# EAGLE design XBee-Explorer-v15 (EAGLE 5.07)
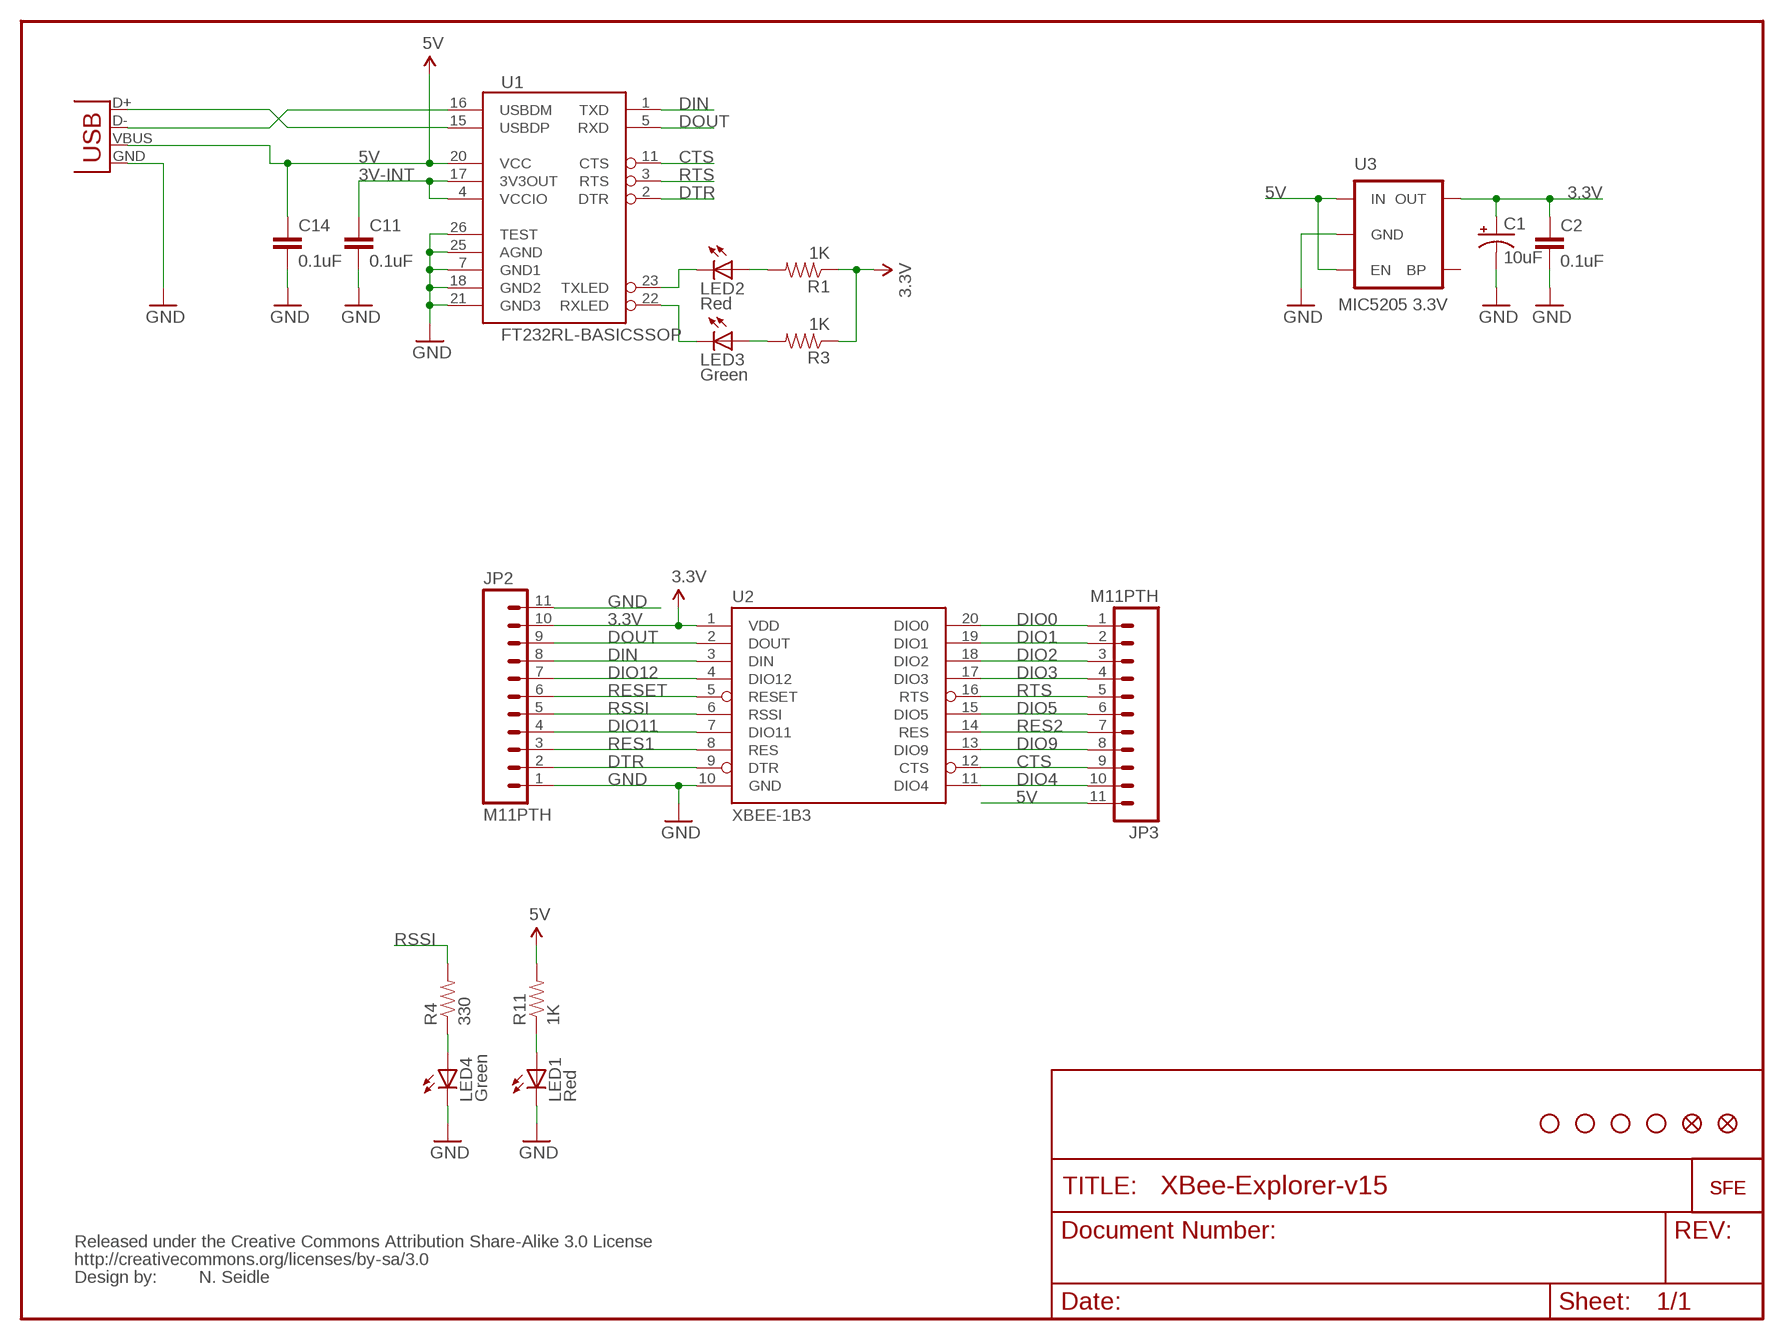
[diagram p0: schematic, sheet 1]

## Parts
C1  10uF  CAP_POL1206  [EIA3216]
C2  0.1uF  CAP0402  [C0402]
C11  0.1uF  CAP0402  [C0402]
C14  0.1uF  CAP0402  [C0402]
JP2  M11PTH  [1X11]
JP3  M11PTH  [1X11]
LED1  Red  LED0603  [LED-0603]
LED2  Red  LED0603  [LED-0603]
LED3  Green  LED0603  [LED-0603]
LED4  Green  LED0603  [LED-0603]
R1  1K  RESISTOR0402  [C0402]
R3  1K  RESISTOR0402  [C0402]
R4  330  RESISTOR0402  [C0402]
R11  1K  RESISTOR0402  [C0402]
U1  FT232RL-BASICSSOP  [SSOP28DB]
U2  XBEE-1B3  [XBEE-SMD]
U3  MIC5205 3.3V  V_REG_LDOSMD  [SOT23-5]
U$1  LOGO-SFESK  [SFE-LOGO-FLAME]
U$2  CREATIVE_COMMONS  [CREATIVE_COMMONS]
U$4  LOGO-SFENEW  [SFE-NEW-WEBLOGO]
U$5  STAND-OFF  [STAND-OFF]
U$7  FIDUCIAL1X2  [FIDUCIAL-1X2]
U$9  STAND-OFF  [STAND-OFF]
U$10  STAND-OFF  [STAND-OFF]
U$11  STAND-OFF  [STAND-OFF]
U$16  FIDUCIAL1X2  [FIDUCIAL-1X2]
X1  USBSMD  [USB-MINIB]

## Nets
3.3V [vcc]: C1.A(+) C2.1 JP2.10 R1.1 R3.1 U2.1(VDD) U3.5(OUT)
3V-INT [vcc]: C11.1 U1.4(VCCIO) U1.17(3V3OUT)
5V [vcc]: C14.1 JP3.11 R11.2 U1.20(VCC) U3.1(IN) U3.3(EN) X1.VBUS
CTS: JP3.9 U1.11(CTS) U2.12(CTS)
DIN: JP2.8 U1.1(TXD) U2.3(DIN)
DIO0: JP3.1 U2.20(DIO0)
DIO1: JP3.2 U2.19(DIO1)
DIO2: JP3.3 U2.18(DIO2)
DIO3: JP3.4 U2.17(DIO3)
DIO4: JP3.10 U2.11(DIO4)
DIO5: JP3.6 U2.15(DIO5)
DIO9: JP3.8 U2.13(DIO9)
DIO11: JP2.4 U2.7(DIO11)
DIO12: JP2.7 U2.4(DIO12)
DOUT: JP2.9 U1.5(RXD) U2.2(DOUT)
DTR: JP2.2 U1.2(DTR) U2.9(DTR)
GND [vcc]: C1.C(-) C2.2 C11.2 C14.2 JP2.1 JP2.11 LED1.C LED4.C U1.7(GND1) U1.18(GND2) U1.21(GND3) U1.25(AGND) U1.26(TEST) U2.10(GND) U3.2(GND) X1.GND
N$1: LED2.A R1.2
N$2: LED4.A R4.1
N$3: U1.16(USBDM) X1.D-
N$4: LED3.A R3.2
N$5: U1.15(USBDP) X1.D+
N$38: LED1.A R11.1
RES1: JP2.3 U2.8(RES)
RES2: JP3.7 U2.14(RES)
RESET: JP2.6 U2.5(RESET)
RSSI: JP2.5 R4.2 U2.6(RSSI)
RTS: JP3.5 U1.3(RTS) U2.16(RTS)
RXLED: LED3.C U1.22(RXLED)
TXLED: LED2.C U1.23(TXLED)
Unconnected: U3.4(BP)

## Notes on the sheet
- N. Seidle

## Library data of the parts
C1 = SparkFun:CAP_POL: Capacitor Polarized
C2 C11 C14 = SparkFun:CAP: Capacitor
JP2 JP3 = SparkFun:M11: Header 11 Standard 11-pin 0.1" header. Use with straight break away headers (SKU : PRT-00116), right angle break away headers (PRT-00553), swiss pins (PRT-00743), machine pins (PRT-00117), and female headers (PRT-00115).
LED1-LED4 = SparkFun:LED: LEDs
R1 R3 R4 R11 = SparkFun:RESISTOR: Resistor
U1 = SparkFun:FT232RL-BASIC: USB UART This is the simplified version of the FT232RL unit. Only what you need, nothing you don't. Spark Fun Electronics SKU : COM-00650
U2 = SparkFun:XBEE-1
U3 = SparkFun:V_REG_LDO: Voltage Regulator LDO Standard 150mA LDO voltage regulator in SOT-23 layout. Micrel part MIC5205. BP (by-pass) pin is used to lower output noise with 470pF cap.
U$1 U$4 = SparkFun:LOGO-SFE: Spark Fun Electronics PCB Logo
U$2 = SparkFun:CREATIVE_COMMONS
U$5 U$9-U$11 = SparkFun:STAND-OFF: Stand Off
U$7 U$16 = SparkFun:FIDUCIAL: Fiducial Alignment Points
X1 = SparkFun:USB: USB Connectors USB-B-PTH is fully proven SKU : PRT-00139 USB-miniB is fully proven SKU : PRT-00587 USB-A-PCB is untested. USB-A-H is throughly reviewed, but untested. Spark Fun Electronics SKU : PRT-00437 USB-B-SMT is throughly reviewed, but untested. Needs silkscreen touching up. USB-A-S has not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

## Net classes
0 default: width 0.203 mm
1 vcc: width 0.305 mm
2 gnd: width 0.254 mm

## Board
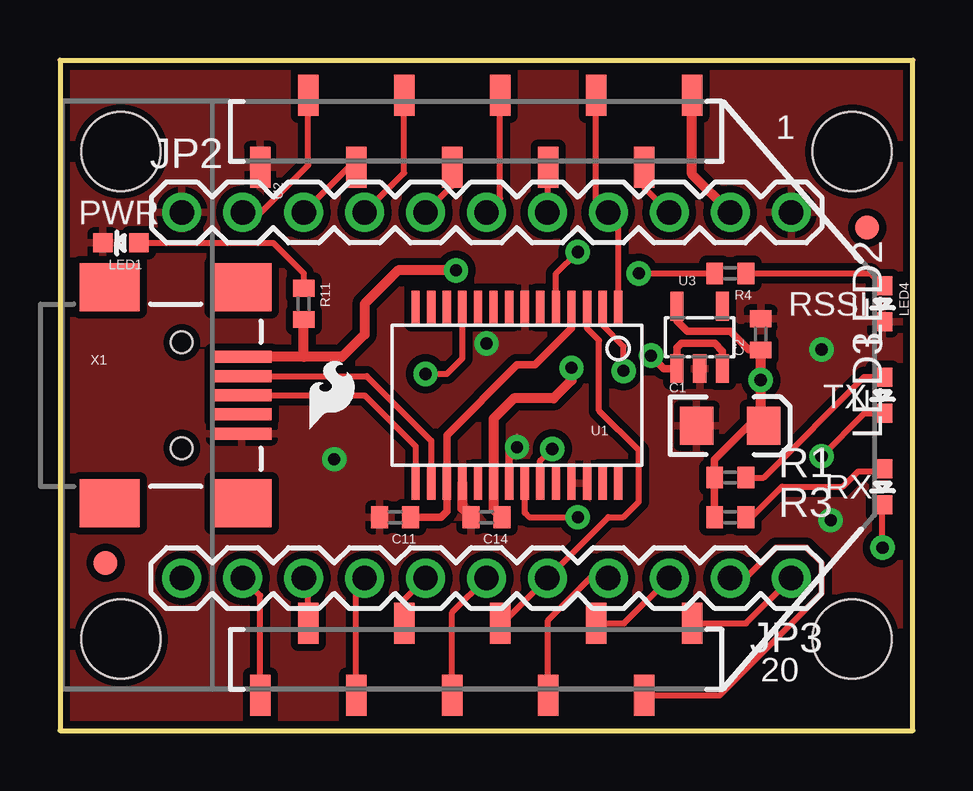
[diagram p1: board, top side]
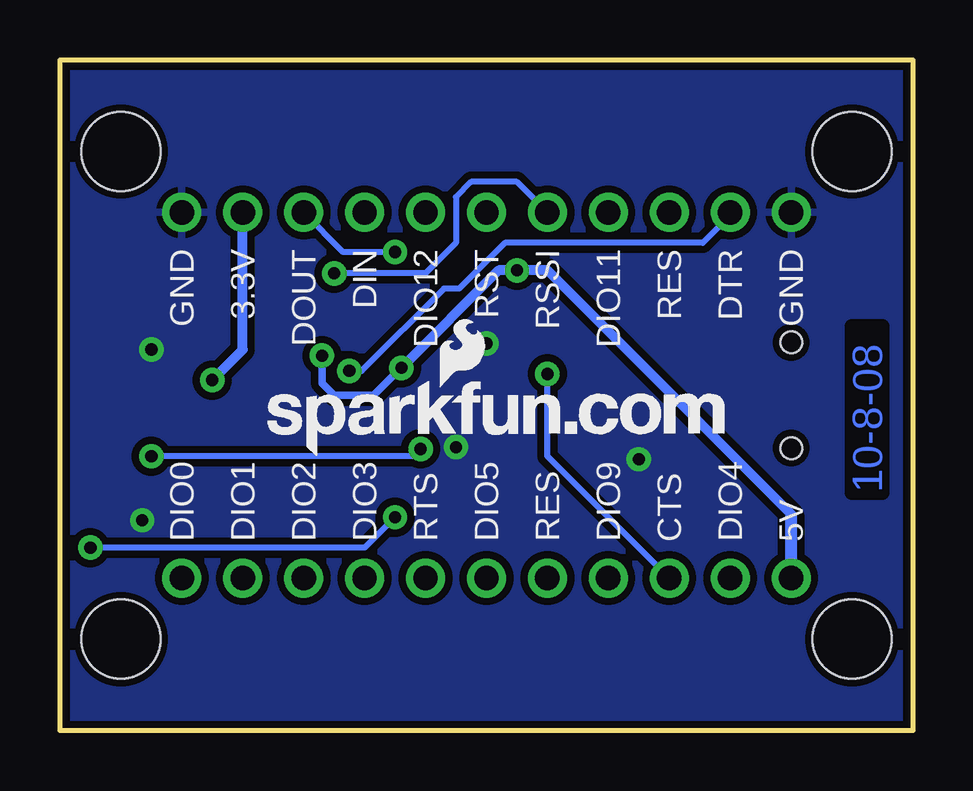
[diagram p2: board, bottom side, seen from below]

Size 35.56 x 27.94 mm. Coordinates in mm from the lower left corner, seen from the top.
Outline: 35.56,0 35.56,27.94 0,27.94 0,0 35.56,0
Copper layers (1*16): Top 0.035mm / dielectric 1.5mm / Bottom 0.035mm
Design rules "SparkFun": minimum track width 8mil, minimum drill 20mil, track to track 8mil, track to pad 8mil, pad to pad 8mil, via to via 8mil, smd to smd 8mil, copper to edge 10mil, drill to drill 8mil, minimum pad ring 12mil, minimum via ring 10mil, stop-mask expansion 4mil, vias tented up to drill 20mil, thermal gap 10mil

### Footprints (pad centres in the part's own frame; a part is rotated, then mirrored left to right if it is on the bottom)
EIA3216 = smd 1.4 x 1.6: A 1.4,0; C -1.4,0
C0402 = smd 0.7 x 0.9: 1 -0.65,0; 2 0.65,0
1X11 = drill 1.016 round: 1 0,0; 2 2.54,0; 3 5.08,0; 4 7.62,0; 5 10.16,0; 6 12.7,0; 7 15.24,0; 8 17.78,0; 9 20.32,0; 10 22.86,0; 11 25.4,0
LED-0603 = smd 0.8 x 0.8: A 0,-0.75; C 0,0.75
SSOP28DB = smd 0.348 x 1.397: 1 -4.225,-3.656; 2 -3.575,-3.656; 3 -2.925,-3.656; 4 -2.275,-3.656; 5 -1.625,-3.656; 6 -0.975,-3.656; 7 -0.325,-3.656; 8 0.325,-3.656; 9 0.975,-3.656; 10 1.625,-3.656; 11 2.275,-3.656; 12 2.925,-3.656; 13 3.575,-3.656; 14 4.225,-3.656; 15 4.225,3.656; 16 3.575,3.656; 17 2.925,3.656; 18 2.275,3.656; 19 1.625,3.656; 20 0.975,3.656; 21 0.325,3.656; 22 -0.325,3.656; 23 -0.975,3.656; 24 -1.625,3.656; 25 -2.275,3.656; 26 -2.925,3.656; 27 -3.575,3.656; 28 -4.225,3.656
XBEE-SMD = smd 1.7 x 0.85: 1 -12.5,20; 2 -9.5,18; 3 -12.5,16; 4 -9.5,14; 5 -12.5,12; 6 -9.5,10; 7 -12.5,8; 8 -9.5,6; 9 -12.5,4; 10 -9.5,2; 11 12.5,2; 12 9.5,4; 13 12.5,6; 14 9.5,8; 15 12.5,10; 16 9.5,12; 17 12.5,14; 18 9.5,16; 19 12.5,18; 20 9.5,20
SOT23-5 = smd 0.55 x 1.2: 1 -0.95,-1.3; 2 0,-1.3; 3 0.95,-1.3; 4 0.95,1.3; 5 -0.95,1.3
STAND-OFF = hole 3.302: 0,0
FIDUCIAL-1X2 = smd 1 x 1: 1 0,0
USB-MINIB = smd 2.5 x 0.5: D+ 2.5,0; D- 2.5,0.8; GND 2.5,-1.6; ID 2.5,-0.8; VBUS 2.5,1.6 | smd 2.5 x 2: GND@1 -3,-4.5; GND@2 -3,4.5; GND@3 2.5,4.5; GND@4 2.5,-4.5 | hole 0.9: 0,2.2; 0,-2.2

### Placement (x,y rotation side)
C1  27.94,12.7 0 top
C2  29.21,16.51 90 top
C11  13.97,8.89 180 top
C14  17.78,8.89 180 top
JP2  5.08,21.59 0 top
JP3  30.48,6.35 180 top
LED1  2.54,20.32 90 top
LED2  34.29,13.97 180 top
LED3  34.29,10.16 180 top
LED4  34.29,17.78 180 top
R1  27.94,10.54 0 top
R3  27.94,8.89 0 top
R4  27.94,19.05 180 top
R11  10.16,17.78 270 top
U1  19.05,13.97 180 top
U2  6.35,13.97 270 top
U3  26.67,16.38 0 top
U$1  10.41,12.57 0 top
U$2  not placed on the board
U$4  26.92,11.43 0 bottom
U$5  2.54,3.81 0 top
U$7  33.66,20.95 0 top
U$9  2.54,24.13 0 top
U$10  33.02,24.13 0 top
U$11  33.02,3.81 0 top
U$16  1.91,6.99 0 top
X1  5.08,13.97 0 top

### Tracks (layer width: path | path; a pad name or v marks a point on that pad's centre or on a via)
3.3V  (via drill 0.51)
  Top 0.305: R1.1 27.3,10.79 | R1.1 27.29,10.68 27.3,10.67 27.29,10.65 R3.1 | R1.1 27.29,11.29 28.7,12.7 C1.A | C2.1 28.72,15.86 27.94,16.64 26.16,16.64 25.72,17.08 U3.5
  Top 0.406: C1.A 29.21,12.7 v29.21,14.61 C2.1 | U2.1 26.35,23.18 JP2.10
  Bottom 0.406: JP2.10 27.94,15.88 v29.21,14.61
3V-INT
  Top 0.305: C11.1 15.88,8.89 16.12,9.14 U1.17 16.12,12.31 19.05,15.24 19.81,15.24 21.32,16.75 U1.4
5V  (via drill 0.51)
  Top 0.305: U3.3 27.62,15.81 27.3,16.13 25.91,16.13 25.72,15.94 U3.1 25.18,15.08 v24.64,15.62
  Top 0.406: C14.1 18.41,8.89 18.07,9.23 U1.20 18.07,12.99 18.92,13.84 20.57,13.84 21.32,14.59 v21.32,15.1 21.34,15.11 v21.32,15.11 | v16.51,19.18 14.1,19.18 12.7,17.78 12.7,16.51 11.76,15.57 10.16,15.57 | 10.16,15.57 X1.VBUS | 10.16,15.57 R11.2
  Bottom 0.305: 21.34,15.11 22.48,13.97 24.13,13.97 24.64,14.48 v24.64,15.62
  Bottom 0.406: 21.34,15.11 v21.32,15.11 21.32,15.12 17.27,19.18 v16.51,19.18 15.24,19.18 5.08,9.02 5.08,8.89
  Bottom 0.508: JP3.11 5.08,8.89
CTS  (via drill 0.51)
  Top 0.254: U1.11 16.77,15.51 16.13,14.86 v15.24,14.86 | U2.12 10.35,6.16 JP3.9
  Bottom 0.254: v15.24,14.86 15.24,11.43 JP3.9
DIN
  Top 0.254: U1.1 23.27,21.18 JP2.8 22.35,22.1 U2.3
DIO0
  Top 0.254: U2.20 28.6,4.47 JP3.1
DIO1
  Top 0.254: U2.19 27.5,1.47 31.75,5.71 31.75,6.99 31.11,7.62 29.84,7.62 28.57,6.35 JP3.2
DIO2
  Top 0.254: U2.18 23.52,4.47 JP3.3
DIO3
  Top 0.254: U2.17 20.35,4.6 22.1,6.35 JP3.4
DIO4
  Top 0.254: U2.11 8.35,5.62 JP3.10
DIO5
  Top 0.254: U2.15 16.35,4.92 JP3.6
DIO9
  Top 0.254: U2.13 12.35,6 JP3.8
DIO11
  Top 0.254: U2.7 14.35,23.24 JP2.4
DIO12
  Top 0.254: U2.4 20.35,21.62 JP2.7
DOUT  (via drill 0.51)
  Top 0.254: U1.5 20.68,19.02 v21.59,19.94 | U2.2 24.35,22.64 JP2.9
  Bottom 0.254: v21.59,19.94 23.75,19.94 JP2.9
DTR  (via drill 0.51)
  Top 0.254: U1.2 22.62,16.87 23.5,16 v23.5,14.99 | JP2.2 8.38,21.59 10.35,23.56 U2.9
  Bottom 0.254: JP2.2 7.62,21.46 8.76,20.32 17.02,20.32 18.92,18.41 19.56,18.41 22.99,14.99 v23.5,14.99
GND  (via drill 0.51)
  Top 0.305: U1.21 18.73,11.87 19.05,12.19
  Top 0.406: C14.2 17.14,8.89 16.77,9.26 U1.18
  other vias: 11.43,11.3 32.13,8.76 17.78,16.13 19.05,11.81 31.75,15.88
  pour Bottom (isolate 0.305): 0,27.94 35.56,27.94 35.56,0 0,0
  pour Top (isolate 0.305): 0,27.94 35.56,27.94 35.56,0 0,0
N$1
  Top 0.254: LED2.A 34.29,14.73 33.53,14.73 29.34,10.54 R1.2
N$2
  Top 0.254: LED4.A 34.29,18.54 33.78,19.05 R4.1
N$3
  Top 0.254: U1.16 15.47,12.08 12.79,14.77 X1.D- | X1.D- 7.53,14.77 | X1.D- 7.62,14.73
N$4
  Top 0.254: LED3.A 34.29,10.79 33.27,10.79 32.64,10.16 30.1,10.16 28.83,8.89 R3.2
N$5
  Top 0.254: X1.D+ 12.7,13.97 14.82,11.85 U1.15 | U1.15 14.86,10.29 | U1.15
N$38
  Top 0.254: R11.1 10.16,19.05 8.89,20.32 LED1.A
RES1
  Top 0.254: U2.8 12.04,23.47 JP2.3
RES2
  Top 0.254: U2.14 14.35,5.46 JP3.7
RESET
  Top 0.254: U2.5 18.35,22.16 JP2.6
RSSI  (via drill 0.51)
  Top 0.254: 27.3,19.05 R4.2 v24.13,19.05 | U2.6 16.35,22.7 JP2.5
  Bottom 0.254: v24.13,19.05 20.32,19.05 19.05,20.32 19.05,22.23 18.41,22.86 16.51,22.86 JP2.5
RTS
  Top 0.254: U1.3 21.98,16.76 22.48,16.26 22.48,13.34 24.13,11.68 24.13,9.53 23.5,8.89 22.86,8.89 JP3.5 18.44,4.47 U2.16
RXLED  (via drill 0.51)
  Top 0.254: U1.22 19.38,9.07 19.56,8.89 v21.59,8.89 | v34.29,7.62 LED3.C
  Bottom 0.254: v34.29,7.62 22.86,7.62 v21.59,8.89
TXLED  (via drill 0.51)
  Top 0.254: LED2.C 33.54,13.22 v31.75,11.43 | U1.23 20.02,10.32 20.02,11.25 20.5,11.73 v20.52,11.73
  Bottom 0.254: v20.52,11.73 20.83,11.43 v31.75,11.43

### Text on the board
Bottom: 10-8-08
tPlace: 1 | PWR | RSSI | TX | RX | 20 | N. Seidle
bPlace: GND | DTR | RES | DIO11 | RSSI | RST | DIO12 | DIN | DOUT | 3.3V | GND | 5V | DIO4 | CTS | DIO9 | RES | DIO5 | RTS | DIO3 | DIO2 | DIO1 | DIO0
tValues: XBee Socket Up | DNP | DNP | XBee Socket Up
